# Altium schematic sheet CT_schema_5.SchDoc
size 383 x 218 mm
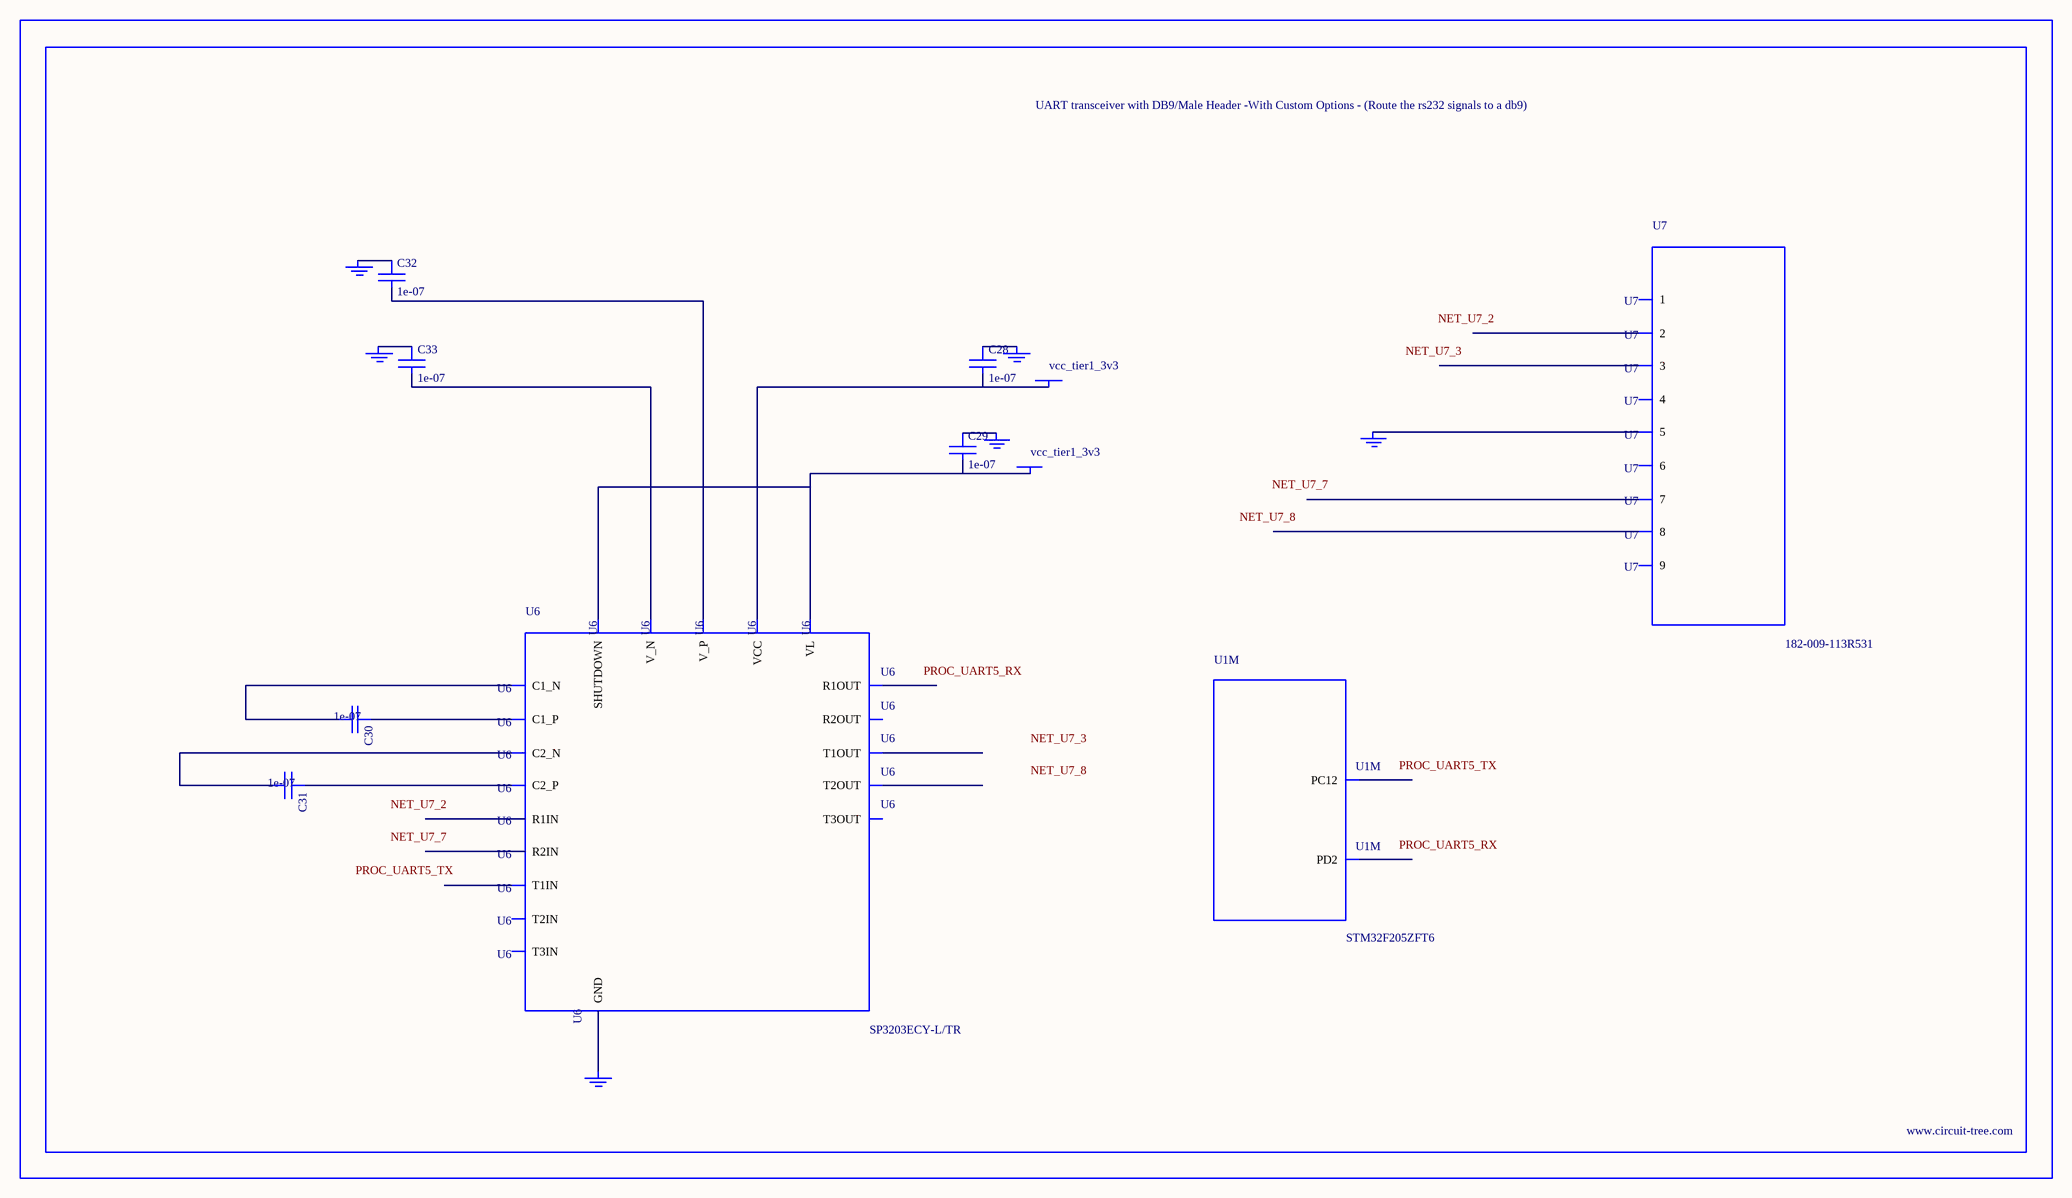
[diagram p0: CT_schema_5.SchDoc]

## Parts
BORDER4  (no value)
C28  1e-07  [C0402]
C29  1e-07  [C0402]
C30  1e-07  [C0402]
C31  1e-07  [C0402]
C32  1e-07  [C0402]
C33  1e-07  [C0402]
GND_INSTANCE_4_0  (no value)
GND_INSTANCE_4_1  (no value)
GND_INSTANCE_4_2  (no value)
GND_INSTANCE_4_3  (no value)
GND_INSTANCE_4_4  (no value)
GND_INSTANCE_4_5  (no value)
POWER_INSTANCE_4_0  vcc_tier1_3v3
POWER_INSTANCE_4_1  vcc_tier1_3v3
U1  STM32F205ZFT6  [LQFP144]  (part M of 13)
U6  SP3203ECY-L/TR  [TSSOP20-I]
U7  182-009-113R531  [182-009-MALE]

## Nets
NetC28_1: C28.1 GND_INSTANCE_4_3.0(GND)
NetC28_2: C28.2 POWER_INSTANCE_4_1.0(PWR) U6.19(VCC)
NetC29_1: C29.1 GND_INSTANCE_4_2.0(GND)
NetC29_2: C29.2 POWER_INSTANCE_4_0.0(PWR) U6.12(VL) U6.20(SHUTDOWN)
NetC30_1: C30.1 U6.1(C1_P)
NetC30_2: C30.2 U6.3(C1_N)
NetC31_1: C31.1 U6.4(C2_P)
NetC31_2: C31.2 U6.5(C2_N)
NetC32_1: C32.1 GND_INSTANCE_4_0.0(GND)
NetC32_2: C32.2 U6.2(V_P)
NetC33_1: C33.1 GND_INSTANCE_4_1.0(GND)
NetC33_2: C33.2 U6.6(V_N)
NetGND_INSTANCE_4_4_0: GND_INSTANCE_4_4.0(GND) U6.18(GND)
NetGND_INSTANCE_4_5_0: GND_INSTANCE_4_5.0(GND) U7.5

Not connected (* = marked no-connect by the designer): U1 113(PC12) 116(PD2); U6 7(T1IN) 8(T2IN) 9(T3IN) 10(R2OUT) 11(R1OUT) 13(R2IN) 14(R1IN) 15(T3OUT) 16(T2OUT) 17(T1OUT); U7 1 2 3 4 6 7 8 9

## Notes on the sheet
- Labels drawn without touching a wire or pin: NET_U7_2, NET_U7_3, NET_U7_7, NET_U7_8, PROC_UART5_RX, PROC_UART5_TX

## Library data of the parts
BORDER4 = BORDER_PAGE4
C28-C33 = C0402C104K3RACTU
GND_INSTANCE_4_0-GND_INSTANCE_4_5 = GND
POWER_INSTANCE_4_0 POWER_INSTANCE_4_1 = PWR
